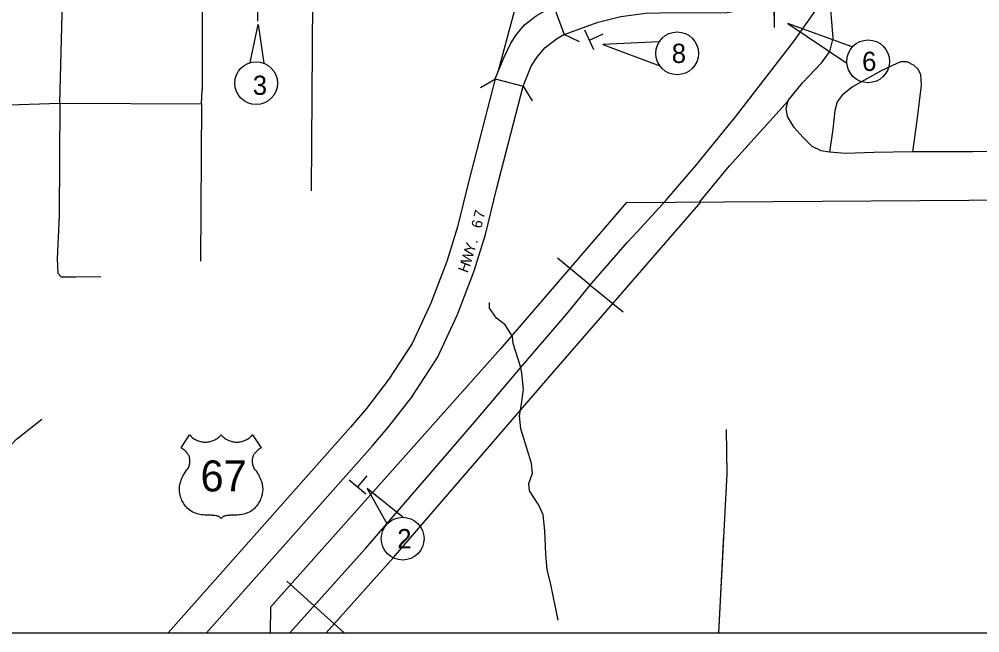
# Model space of a CAD drawing. Extents: x 988392 to 996681, y 1838707 to 1844440.
# Drawn here: x 991180 to 994176, y 1838707 to 1840620 of the extents above; entities that cross this region are included whole.
import ezdxf

# ---------------------------------------------------------------- set-up
doc = ezdxf.new("R2010")
doc.units = 0
for name, color, linetype in [('G-Border-Sheet', 7, 'Continuous'), ('Level 15', 7, 'Continuous'), ('Level 22', 7, 'Continuous'), ('Level 3', 7, 'Continuous'), ('Level 31', 7, 'Continuous'), ('Level 32', 7, 'Continuous'), ('Level 33', 7, 'Continuous'), ('Level 34', 7, 'Continuous'), ('Level 35', 7, 'Continuous'), ('Level 37', 7, 'Continuous'), ('Level 40', 7, 'Continuous'), ('Level 43', 7, 'Continuous'), ('Level 49', 7, 'Continuous'), ('Level 6', 7, 'Continuous'), ('Level 8', 7, 'Continuous'), ('R_Draft', 7, 'Continuous')]:
    doc.layers.add(name, color=color, linetype=linetype)

msp = doc.modelspace()

# ---------------------------------------------------------------- linework, layer by layer
at = {"layer": 'G-Border-Sheet'}
msp.add_lwpolyline([(995124.8, 1844439.6), (989844.9, 1844439.6), (989844.9, 1838706.8), (995124.8, 1838706.8)], close=True, dxfattribs=at)
at = {"layer": 'Level 15'}
for points in [[(992664.9, 1840434.3), (992691.2, 1840499.2), (992713.9, 1840545.4), (992731.6, 1840572), (992756.2, 1840602.1), (992792.3, 1840630.8), (992819.9, 1840646), (992849.7, 1840656.9)], [(992751.9, 1840411.4), (992777.1, 1840474), (992794.7, 1840500.5), (992819.4, 1840530.7), (992855.4, 1840559.4), (992879.1, 1840572.4)]]:
    msp.add_lwpolyline(points, dxfattribs=at)
at = {"layer": 'Level 3'}
for p, q in [((991924.3, 1840614.4), (991923.9, 1840671.1)), ((993535.6, 1840594.2), (993535.2, 1840661.7)), ((993535.7, 1840597), (993535.3, 1840658.8)), ((992972.3, 1840524.2), (992944.2, 1840585.6)), ((992959.2, 1840555.1), (993001.1, 1840574.2)), ((992261, 1839139), (992209.5, 1839182.7)), ((992236, 1839161.5), (992265.8, 1839196.6))]:
    msp.add_line(p, q, dxfattribs=at)
at = {"layer": 'Level 31'}
for points in [[(993296, 1840169.9), (993414.4, 1840315.7), (993597.7, 1840553.9), (993810, 1840856.5), (994001.1, 1841134.2), (994129.9, 1841273.7)], [(993296, 1840169.9), (993414.4, 1840315.7), (993597.7, 1840553.9), (993810, 1840856.5), (994001.1, 1841134.2), (994129.9, 1841273.7)], [(992902.6, 1839719.4), (992964.9, 1839795.7), (993077.8, 1839924.5), (993120.3, 1839970.5), (993196.8, 1840055.2), (993297.8, 1840172)], [(992902.6, 1839719.4), (992964.9, 1839795.7), (993077.8, 1839924.5), (993120.3, 1839970.5), (993196.8, 1840055.2), (993297.8, 1840172)], [(992261.6, 1838971.1), (992470.1, 1839212.4), (992599.8, 1839363.7), (992744.1, 1839533), (992887.6, 1839701.8)], [(992261.6, 1838971.1), (992470.1, 1839212.4), (992599.8, 1839363.7), (992744.1, 1839533), (992887.6, 1839701.8)], [(992024.1, 1838706.8), (992259.3, 1838968.5)], [(992059.7, 1838746.4), (992259.3, 1838968.5)]]:
    msp.add_lwpolyline(points, dxfattribs=at)
at = {"layer": 'Level 32'}
msp.add_lwpolyline([(992137.9, 1838706.8), (992347, 1838941.7), (992829, 1839499.8), (993306.4, 1840049.6)], dxfattribs=at)
at = {"layer": 'Level 33'}
for points in [[(993597.2, 1840282.6), (993576.2, 1840316.9), (993571.8, 1840342.7), (993578.5, 1840366.3), (993623.3, 1840421.2), (993683.8, 1840485.1), (993708.4, 1840519.9), (993718.5, 1840561.4), (993707.2, 1840703.8)], [(991306.3, 1840358.7), (991315.6, 1840674.9)], [(991751.2, 1840677), (991751.2, 1840489.5), (991751.2, 1840400.1)], [(992094.9, 1840680.4), (992091.1, 1840085.4)], [(990648.7, 1840338.5), (990955.7, 1840346.4), (991306.3, 1840358.7), (991748.9, 1840356.5), (991751.2, 1840400.1)], [(991306.3, 1840358.7), (991305, 1840008.2), (991298.3, 1839872.5), (991300.5, 1839827.7), (991310.6, 1839816.5), (991356.5, 1839816.5), (991435, 1839817.6)], [(991748.9, 1840356.5), (991745.3, 1839865.8)], [(994590.7, 1840207.6), (994406.9, 1840208.7), (994153.7, 1840206.5), (993966.9, 1840206.5), (993845.7, 1840204.2), (993757.2, 1840200.9), (993707, 1840205.3), (993681, 1840209.8), (993653, 1840223.3), (993625, 1840251.3), (993597.2, 1840282.6)]]:
    msp.add_lwpolyline(points, dxfattribs=at)
at = {"layer": 'Level 34'}
for points in [[(993966.9, 1840206.5), (993980.3, 1840304), (993993.8, 1840413.9), (993992.7, 1840447.5), (993982.6, 1840465.5), (993971.4, 1840475.6), (993950.1, 1840486.8), (993929.9, 1840486.8), (993917.6, 1840482.3), (993868.3, 1840458.8), (993778.7, 1840409.4), (993747.3, 1840383.6), (993731.6, 1840362.3), (993723.8, 1840335.4), (993718.2, 1840277.1), (993707, 1840205.3)], [(993302.4, 1840049.6), (993395.4, 1840163.1), (993578.4, 1840366)]]:
    msp.add_lwpolyline(points, dxfattribs=at)
at = {"layer": 'Level 35'}
for points in [[(992770, 1839172.5), (992780.6, 1839204.4), (992778, 1839235), (992768.7, 1839265.5), (992744.8, 1839342.6), (992740.8, 1839383.8), (992746.1, 1839413.1), (992752.7, 1839465.4), (992747.4, 1839515.9), (992743.4, 1839537.2), (992720.9, 1839609), (992718.2, 1839630.2), (992695.6, 1839667.5), (992669.1, 1839687.4), (992646.5, 1839719.3), (992647, 1839736.2)], [(990691.9, 1838887), (990768.1, 1838919.6), (990823.8, 1838982.2), (990856.4, 1839014.9), (990887.7, 1839043.5), (990946.2, 1839108.8), (991065.8, 1839198.6), (991171.8, 1839310.2), (991250.7, 1839372.8)], [(992861, 1838746.4), (992837.7, 1838857.5), (992827.1, 1838904), (992823.1, 1838951.9), (992819.1, 1839025), (992813.8, 1839074.1), (992800.6, 1839104.7), (992771.3, 1839149.9), (992770, 1839172.5)]]:
    msp.add_lwpolyline(points, dxfattribs=at)
at = {"layer": 'Level 37'}
for points in [[(992927.5, 1840549.5), (992879.3, 1840571.9)], [(992618.7, 1840407.1), (992665.3, 1840434.4)], [(992752.3, 1840411.8), (992779.6, 1840365.3)]]:
    msp.add_lwpolyline(points, dxfattribs=at)
at = {"layer": 'Level 40'}
for p, q in [((992961.1, 1839791), (992858.8, 1839874.5)), ((992961.1, 1839791), (993063.3, 1839707.5)), ((992099.7, 1838790.9), (992014.3, 1838867.6)), ((992099.7, 1838790.9), (992193.2, 1838706.8))]:
    msp.add_line(p, q, dxfattribs=at)
for points in [[(992024.1, 1838706.8), (992259.3, 1838968.5), (992261.6, 1838971.1), (992470.1, 1839212.4), (992599.8, 1839363.7), (992744.1, 1839533), (992887.6, 1839701.8), (992902.6, 1839719.4), (992964.9, 1839795.7), (993077.8, 1839924.5), (993120.3, 1839970.5), (993196.8, 1840055.2), (993297.8, 1840172), (993296, 1840169.9), (993414.4, 1840315.7), (993597.7, 1840553.9), (993810, 1840856.5)], [(992059.7, 1838746.4), (992259.3, 1838968.5), (992261.6, 1838971.1), (992470.1, 1839212.4), (992599.8, 1839363.7), (992744.1, 1839533), (992887.6, 1839701.8), (992902.6, 1839719.4), (992964.9, 1839795.7), (993077.8, 1839924.5), (993120.3, 1839970.5), (993196.8, 1840055.2), (993297.8, 1840172), (993296, 1840169.9), (993414.4, 1840315.7), (993597.7, 1840553.9), (993810, 1840856.5)]]:
    msp.add_lwpolyline(points, dxfattribs=at)
at = {"layer": 'Level 43'}
for points in [[(993385.5, 1839340.5), (993386.8, 1839202.2), (993361.1, 1838706.8)], [(993385.5, 1839340.5), (993386.8, 1839202.2), (993383.7, 1839142.6)], [(993385.5, 1839340.5), (993386.8, 1839202.2), (993383.7, 1839142.6)], [(993376.9, 1839010.7), (993361.1, 1838706.8)], [(993376.9, 1839010.7), (993363.1, 1838746.4)]]:
    msp.add_lwpolyline(points, dxfattribs=at)
at = {"layer": 'Level 49'}
for points in [[(991711.8, 1839089.1), (991708.6, 1839091.8), (991705.5, 1839094.6), (991701.9, 1839098.4), (991699.1, 1839101.7), (991696.6, 1839104.9), (991694, 1839108.6), (991691.5, 1839112.6), (991689.6, 1839116.1), (991687.8, 1839119.7), (991686.3, 1839123.2), (991684.6, 1839127.9), (991683.4, 1839131.8), (991682.5, 1839134.9), (991681.8, 1839137.6), (991681.1, 1839140.8), (991680.4, 1839144.9), (991679.9, 1839149.3), (991679.8, 1839153.1), (991679.8, 1839156.9), (991680, 1839161), (991680.4, 1839164.7), (991681, 1839168.3), (991681.9, 1839172.3), (991682.9, 1839175.7), (991683.9, 1839178.9), (991685.2, 1839182.7), (991686.4, 1839185.8), (991687.4, 1839188.3), (991688.8, 1839191.5), (991690.4, 1839194.8), (991691.9, 1839197.7), (991693.2, 1839200.1), (991694.7, 1839202.7), (991696.5, 1839205.5), (991698.5, 1839208.4), (991700.6, 1839211.4), (991703.2, 1839214.7), (991705.3, 1839217.2), (991707.1, 1839220.1), (991708.8, 1839223.7), (991709.9, 1839226.5), (991710.7, 1839228.9), (991711.4, 1839231.8), (991711.9, 1839234.4), (991712.3, 1839237.2), (991712.5, 1839239.5), (991712.6, 1839242.3), (991712.4, 1839245.3), (991712.1, 1839248.5), (991711.5, 1839251.8), (991710.8, 1839255), (991709.7, 1839258.2), (991708.4, 1839260.8), (991706.9, 1839263), (991705.4, 1839265.1), (991703.9, 1839267), (991702.4, 1839268.8), (991700.3, 1839271.2), (991698.3, 1839273.2), (991696.3, 1839275.1), (991694, 1839277.1), (991691.2, 1839279.3), (991689, 1839280.8), (991686.8, 1839282.3), (991684.9, 1839283.4), (991711.3, 1839324.3), (991712.9, 1839322.5), (991714.9, 1839320.4), (991716.9, 1839318.5), (991718.8, 1839316.8), (991721.1, 1839314.9), (991723.8, 1839312.9), (991726.7, 1839311), (991729.3, 1839309.5), (991732.2, 1839308), (991735.3, 1839306.5), (991738.7, 1839305.2), (991742.7, 1839303.9), (991746, 1839303), (991749.6, 1839302.3), (991752.4, 1839301.9), (991755.2, 1839301.6), (991758.1, 1839301.4), (991761.5, 1839301.4), (991765.7, 1839301.6), (991768.7, 1839301.9), (991772, 1839302.4), (991775.1, 1839303), (991778.5, 1839303.9), (991782.2, 1839305.1), (991785.5, 1839306.4), (991789.8, 1839308.4), (991793.2, 1839310.2), (991796.1, 1839312.1), (991798.9, 1839314), (991801.2, 1839315.8), (991803.5, 1839317.8), (991805.7, 1839319.8), (991807.6, 1839321.8), (991809.6, 1839324.1)], [(991809.6, 1839324.1), (991811.7, 1839321.8), (991813.6, 1839319.8), (991815.8, 1839317.8), (991818.1, 1839315.8), (991820.4, 1839314), (991823.1, 1839312.1), (991826.1, 1839310.2), (991829.5, 1839308.4), (991833.8, 1839306.4), (991837, 1839305.1), (991840.8, 1839303.9), (991844.1, 1839303), (991847.3, 1839302.4), (991850.6, 1839301.9), (991853.6, 1839301.6), (991857.8, 1839301.4), (991861.2, 1839301.4), (991864.1, 1839301.6), (991866.9, 1839301.9), (991869.7, 1839302.3), (991873.3, 1839303), (991876.6, 1839303.9), (991880.6, 1839305.2), (991884, 1839306.5), (991887.1, 1839308), (991889.9, 1839309.5), (991892.6, 1839311), (991895.5, 1839312.9), (991898.2, 1839314.9), (991900.5, 1839316.8), (991902.4, 1839318.5), (991904.4, 1839320.4), (991906.4, 1839322.5), (991907.9, 1839324.3), (991934.4, 1839283.4), (991932.5, 1839282.3), (991930.2, 1839280.8), (991928.1, 1839279.3), (991925.3, 1839277.1), (991923, 1839275.1), (991921, 1839273.2), (991919, 1839271.2), (991916.9, 1839268.8), (991915.3, 1839267), (991913.9, 1839265.1), (991912.4, 1839263), (991910.9, 1839260.8), (991909.5, 1839258.2), (991908.5, 1839255), (991907.7, 1839251.8), (991907.2, 1839248.5), (991906.8, 1839245.3), (991906.7, 1839242.3), (991906.8, 1839239.5), (991907, 1839237.2), (991907.4, 1839234.4), (991907.9, 1839231.8), (991908.6, 1839228.9), (991909.4, 1839226.5), (991910.5, 1839223.7), (991912.2, 1839220.1), (991914, 1839217.2), (991916.1, 1839214.7), (991918.7, 1839211.4), (991920.8, 1839208.4), (991922.8, 1839205.5), (991924.6, 1839202.7), (991926.1, 1839200.1), (991927.4, 1839197.7), (991928.9, 1839194.8), (991930.5, 1839191.5), (991931.9, 1839188.3), (991932.9, 1839185.8), (991934.1, 1839182.7), (991935.4, 1839178.9), (991936.4, 1839175.7), (991937.4, 1839172.3), (991938.2, 1839168.3), (991938.8, 1839164.7), (991939.3, 1839161), (991939.5, 1839156.9), (991939.5, 1839153.1), (991939.3, 1839149.3), (991938.9, 1839144.9), (991938.2, 1839140.8), (991937.5, 1839137.6), (991936.8, 1839134.9), (991935.9, 1839131.8), (991934.7, 1839127.9), (991932.9, 1839123.2), (991931.4, 1839119.7), (991929.7, 1839116.1), (991927.8, 1839112.6), (991925.3, 1839108.6), (991922.7, 1839104.9), (991920.2, 1839101.7), (991917.4, 1839098.4), (991913.7, 1839094.6), (991910.6, 1839091.8), (991907.4, 1839089.1)], [(991809.6, 1839061.9), (991808.5, 1839063.8), (991807.2, 1839065.5), (991805.6, 1839067.1), (991804, 1839068.4), (991802.8, 1839069.2), (991801.4, 1839069.9), (991799, 1839070.9), (991797, 1839071.3), (991794.6, 1839071.7), (991790.6, 1839072.2), (991786.5, 1839072.6), (991783.2, 1839072.9), (991780, 1839073.1), (991776.2, 1839073.3), (991772.3, 1839073.4), (991768.4, 1839073.4), (991764.3, 1839073.4), (991759.6, 1839073.6), (991753.4, 1839074.1), (991748.5, 1839074.8), (991743.9, 1839075.6), (991739.1, 1839076.7), (991734.8, 1839077.9), (991730, 1839079.5), (991724.1, 1839081.7), (991719.1, 1839084), (991715.2, 1839086.6), (991711.8, 1839089.1)], [(991907.4, 1839089.1), (991904.1, 1839086.6), (991900.1, 1839084), (991895.1, 1839081.7), (991889.3, 1839079.5), (991884.5, 1839077.9), (991880.2, 1839076.7), (991875.3, 1839075.6), (991870.8, 1839074.8), (991865.9, 1839074.1), (991859.7, 1839073.6), (991855, 1839073.4), (991850.9, 1839073.4), (991847, 1839073.4), (991843, 1839073.3), (991839.3, 1839073.1), (991836, 1839072.9), (991832.8, 1839072.6), (991828.7, 1839072.2), (991824.7, 1839071.7), (991822.3, 1839071.3), (991820.3, 1839070.9), (991817.9, 1839069.9), (991816.5, 1839069.2), (991815.3, 1839068.4), (991813.7, 1839067.1), (991812.1, 1839065.5), (991810.8, 1839063.8), (991809.6, 1839061.9)]]:
    msp.add_lwpolyline(points, dxfattribs=at)
at = {"layer": 'Level 6'}
for points in [[(994605.4, 1840619.7), (994600.2, 1840058.2), (993073.2, 1840048), (992681.4, 1839592.2), (991963.8, 1838786.5), (991963.2, 1838706.8)], [(994605.4, 1840619.6), (994600.2, 1840058.2), (993073.2, 1840048), (992681.4, 1839592.2), (991963.8, 1838786.5), (991963.2, 1838706.8)], [(994605.3, 1840618.1), (994600.2, 1840058.2), (993073.2, 1840048), (992681.4, 1839592.2), (991963.8, 1838786.5), (991963.2, 1838706.8)]]:
    msp.add_lwpolyline(points, dxfattribs=at)
at = {"layer": 'Level 8'}
for points in [[(991900.2, 1840484.7), (991925.7, 1840603.6), (991942.7, 1840483)], [(993778.5, 1840533.7), (993577.2, 1840606.8), (993761.3, 1840482.7)], [(993176.3, 1840549.8), (993000.3, 1840541.6), (993178.3, 1840474.4)], [(992376.1, 1839067), (992265.6, 1839157.1), (992327.5, 1839045.9)]]:
    msp.add_lwpolyline(points, dxfattribs=at)
for centre in [(993232.3, 1840513.6), (993827.7, 1840488.7), (991919, 1840420.7), (992376.1, 1839000.3)]:
    msp.add_circle(centre, 66.7, dxfattribs=at)
at = {"layer": 'R_Draft'}
for p, q in [((992673.8, 1840456.4), (992767.1, 1840802.9)), ((992848.9, 1840656.6), (992879.3, 1840571.9)), ((992664.9, 1840434.3), (992751.9, 1840411.4)), ((992664.9, 1840434.3), (992751.9, 1840411.4))]:
    msp.add_line(p, q, dxfattribs=at)
for points in [[(992879.3, 1840571.9), (992985.6, 1840610.6), (993056.1, 1840628.5), (993134.8, 1840638.9), (993177.2, 1840640.2), (993386.8, 1840641.5), (993456.2, 1840652.3), (993509, 1840672), (993542, 1840705.1), (993571.7, 1840740.8), (993579.5, 1840789.6), (993583.8, 1840873.8), (993586.2, 1841123.4), (993587.6, 1841363.1), (993584.3, 1841942.6), (993584.4, 1842099.3)], [(992664.9, 1840434.4), (992581.4, 1840111.7), (992547.4, 1839972.9), (992514, 1839864.6), (992464.4, 1839734.5), (992406.2, 1839608.8), (992331.3, 1839494.4)], [(992403.9, 1839440.9), (992485.1, 1839565), (992547.4, 1839699.6), (992599.1, 1839835.3), (992634.2, 1839948.9), (992668.7, 1840089.7), (992751.9, 1840411.5)], [(992333.4, 1839497.3), (992262.8, 1839406.3), (992213.1, 1839347.9), (991644.4, 1838706.8)], [(991764.7, 1838706.8), (992281.1, 1839288.9), (992332.7, 1839349.6), (992407.6, 1839446.1)]]:
    msp.add_lwpolyline(points, dxfattribs=at)

# ---------------------------------------------------------------- texts
at = {"layer": 'Level 22'}
msp.add_text('67', height=96.8, dxfattribs=at).set_placement((991745.7, 1839147.6))
at = {"layer": 'Level 8'}
for s, p in [('8', (993215.3, 1840483.6)), ('6', (993809, 1840458.7)), ('3', (991908.5, 1840384.1)), ('2', (992359.1, 1838970.3))]:
    msp.add_text(s, height=60, dxfattribs=at).set_placement(p)
at = {"layer": 'R_Draft'}
for s, rotation, p in [('7', 76.2347, (992628.8, 1839996.3)), ('6', 76.2347, (992621.4, 1839966)), ('Y', 72.8552, (992598.3, 1839888.6)), ('.', 72.8552, (992607.7, 1839918.9)), ('W', 72.8552, (992587.9, 1839854.8)), ('H', 69.13, (992578.3, 1839826.8))]:
    msp.add_text(s, height=33, rotation=rotation, dxfattribs=at).set_placement(p)

doc.saveas('drawing.dxf')
